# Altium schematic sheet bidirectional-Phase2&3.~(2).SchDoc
size 431 x 279 mm; Date: Not shown in title block; ApprovedBy: Not shown in title block; CheckedBy: Not shown in title block; Author: Not shown in title block; CompanyName: Not shown in title block; Engineer: Not shown in title block; Organization: Not shown in title block; Address1: Not shown in title block; Address2: Not shown in title block; Address3: Not shown in title block; Address4: Not shown in title block; DocumentNumber: 5; Revision: Use project parameter SCH_Rev; SheetNumber: 5; SheetTotal: 6; PageSetup: Record=PageOptions|CenterHorizontal=True|CenterVertical=True|PrintScale=0.96|XCorrection=1.00|YCorrection=1.00|PrintKind=0|BorderSize=5000000|LeftOffset=0|BottomOffset=0|Orientation=2|PaperLength=1000|PaperWidth=1000|Scale=100|PaperSource=15|PrintQuality=600|MediaType=1|DitherType=10|PaperKind=11x17|PrintScaleMode=1
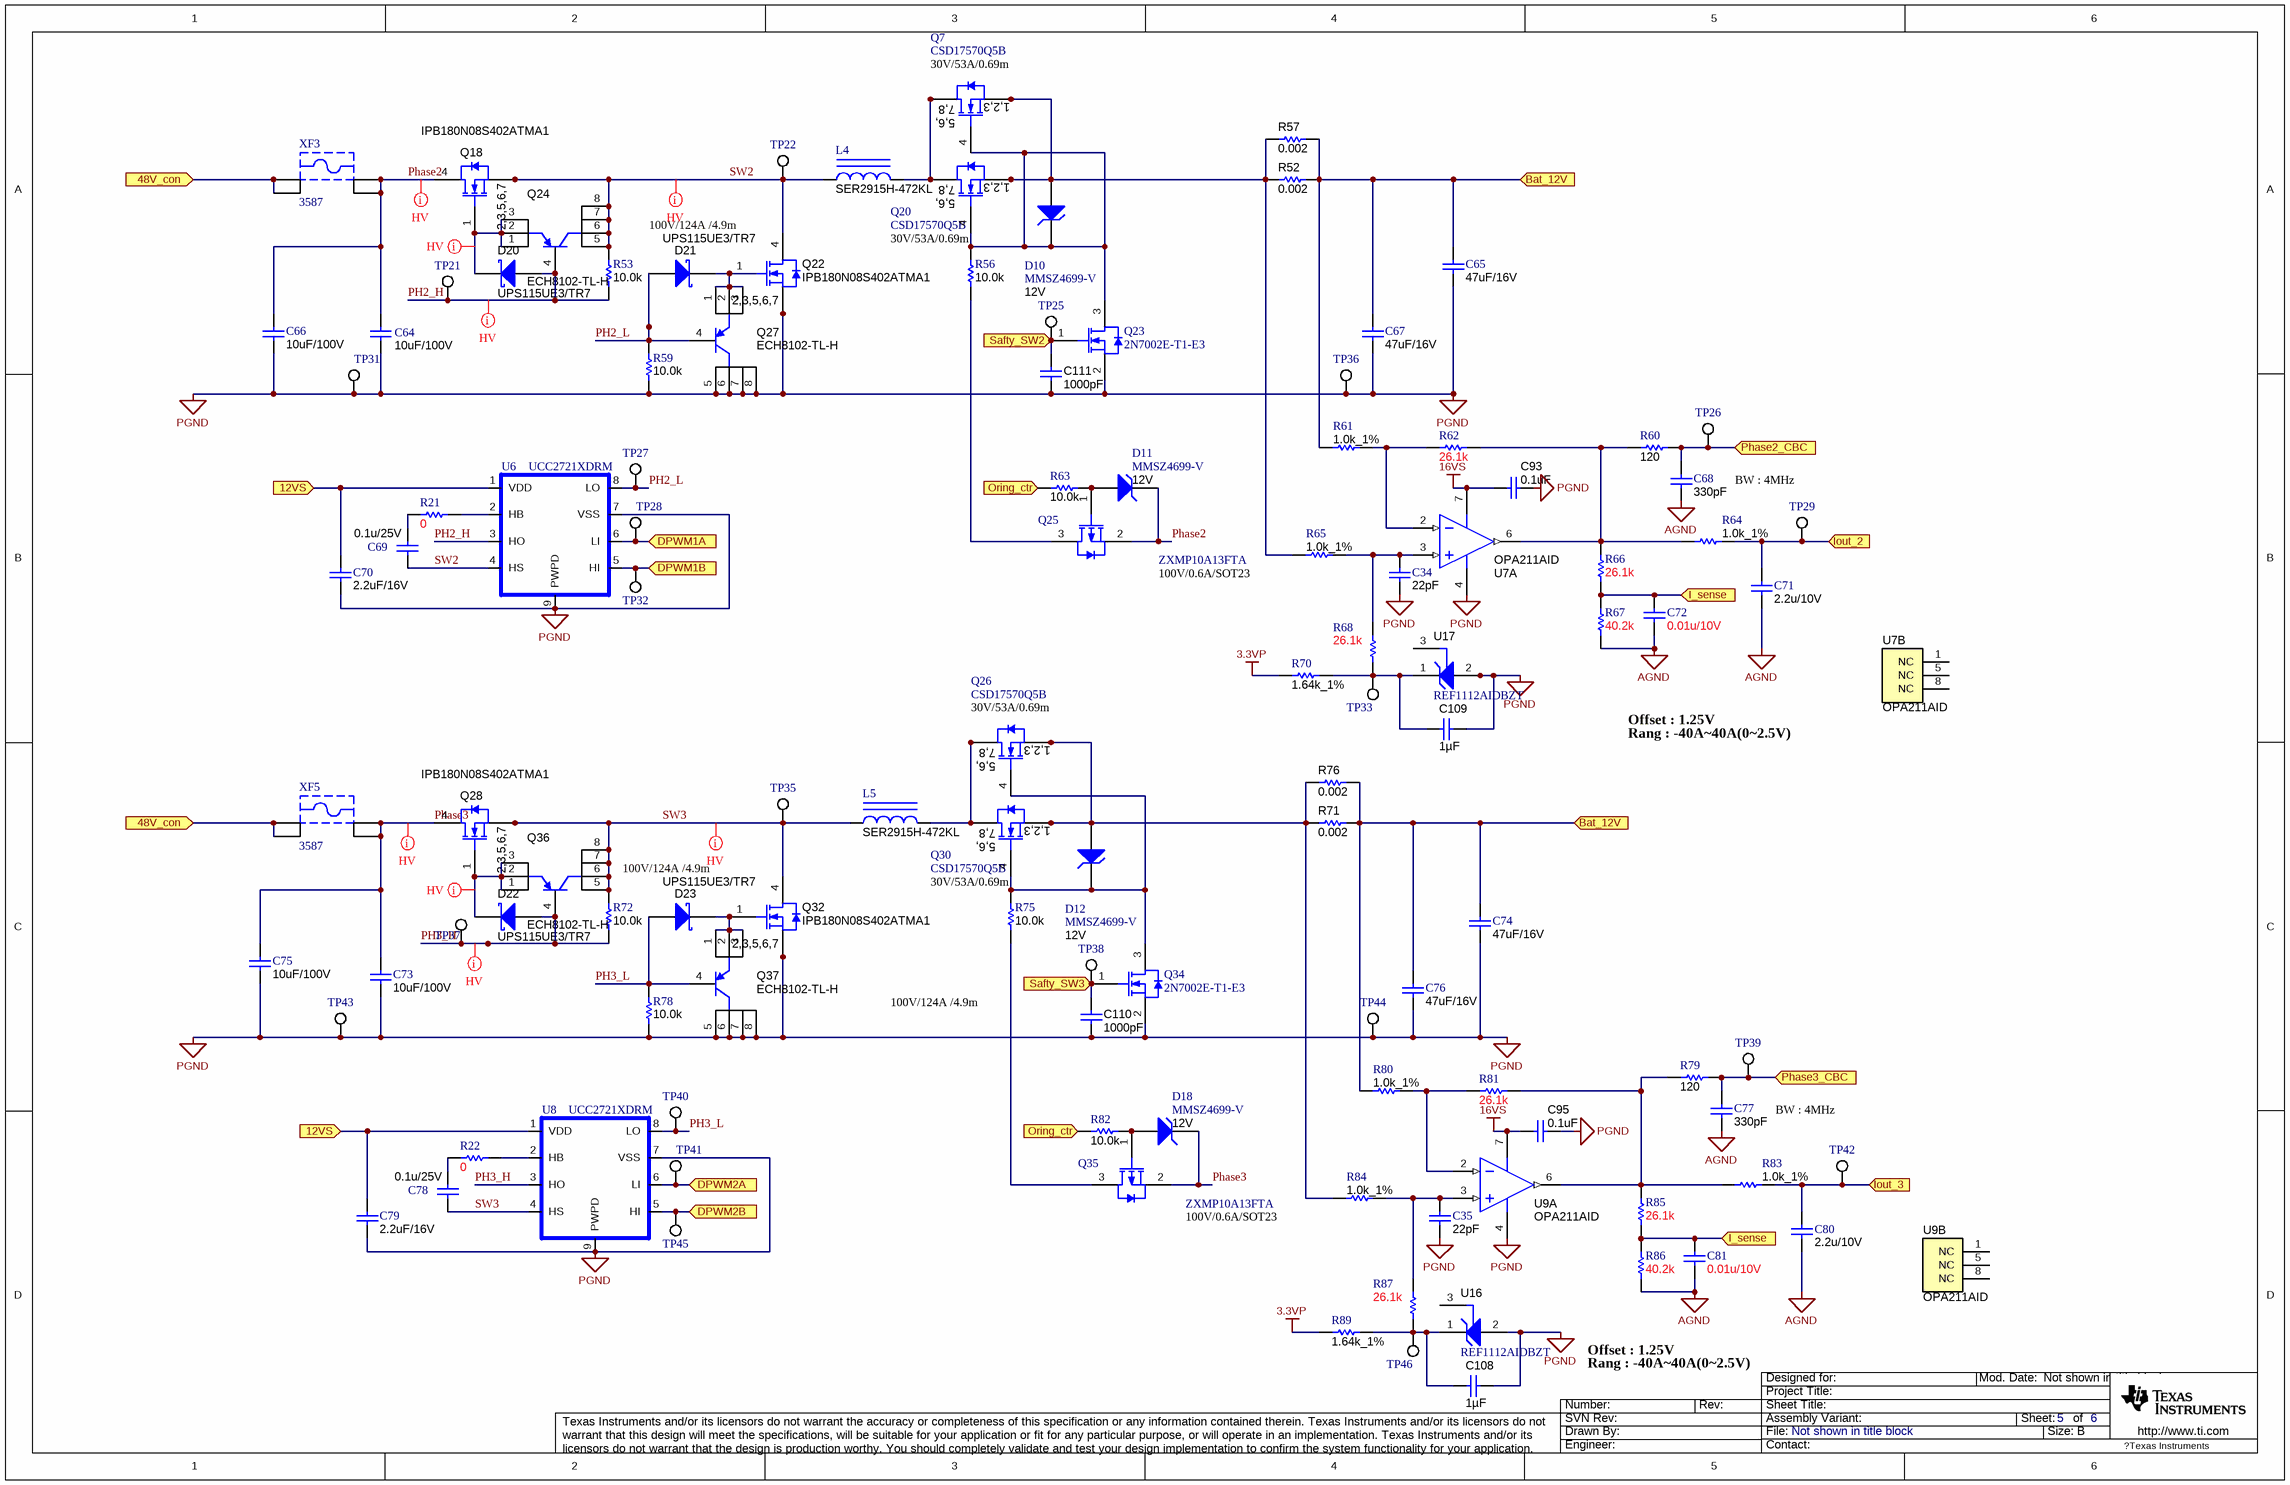
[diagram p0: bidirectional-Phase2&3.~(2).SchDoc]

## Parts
C34  ValueDisplayed: 22pF  [0603]  (hidden comment: 06035A220JAT2A)
C35  ValueDisplayed: 22pF  [0603]  (hidden comment: 06035A220JAT2A)
C64  ValueDisplayed: 10uF/100V  [2220]  (hidden comment: C5750X7S2A106M)
C65  ValueDisplayed: 47uF/16V  [1210]  (hidden comment: GRM32ER61C476ME15L)
C66  ValueDisplayed: 10uF/100V  [2220]  (hidden comment: C5750X7S2A106M)
C67  ValueDisplayed: 47uF/16V  [1210]  (hidden comment: GRM32ER61C476ME15L)
C68  ValueDisplayed: 330pF  [0603]  (hidden comment: 06035A331JAT2A)
C69  ValueDisplayed: 0.1u/25V  [0603]  (hidden comment: 06033C104KAT2A)
C70  ValueDisplayed: 2.2uF/16V  [0805_HV]  (hidden comment: 0805YD225KAT2A)
C71  ValueDisplayed: 2.2u/10V  [0603]  (hidden comment: C0603C225K8PACTU)
C72  ValueDisplayed: 0.01u/10V  [0603]  (hidden comment: 06031C103JAT2A)
C73  ValueDisplayed: 10uF/100V  [2220]  (hidden comment: C5750X7S2A106M)
C74  ValueDisplayed: 47uF/16V  [1210]  (hidden comment: GRM32ER61C476ME15L)
C75  ValueDisplayed: 10uF/100V  [2220]  (hidden comment: C5750X7S2A106M)
C76  ValueDisplayed: 47uF/16V  [1210]  (hidden comment: GRM32ER61C476ME15L)
C77  ValueDisplayed: 330pF  [0603]  (hidden comment: 06035A331JAT2A)
C78  ValueDisplayed: 0.1u/25V  [0603]  (hidden comment: 06033C104KAT2A)
C79  ValueDisplayed: 2.2uF/16V  [0805_HV]  (hidden comment: 0805YD225KAT2A)
C80  ValueDisplayed: 2.2u/10V  [0603]  (hidden comment: C0603C225K8PACTU)
C81  ValueDisplayed: 0.01u/10V  [0603]  (hidden comment: 06031C103JAT2A)
C93  ValueDisplayed: 0.1uF  [0603]  (hidden comment: 06033C104JAT2A)
C95  ValueDisplayed: 0.1uF  [0603]  (hidden comment: 06033C104JAT2A)
C108  ValueDisplayed: 1µF  [0603_095]  (hidden comment: C0603C105K3RACTU)
C109  ValueDisplayed: 1µF  [0603_095]  (hidden comment: C0603C105K3RACTU)
C110  ValueDisplayed: 1000pF  [0603]  (hidden comment: C0603X102K5RACTU)
C111  ValueDisplayed: 1000pF  [0603]  (hidden comment: C0603X102K5RACTU)
D10  MMSZ4699-V  value 12V  [SOD-123]
D11  MMSZ4699-V  value 12V  [SOD-123]
D12  MMSZ4699-V  value 12V  [SOD-123]
D18  MMSZ4699-V  value 12V  [SOD-123]
D20  UPS115UE3/TR7  [DO-216AA]
D21  UPS115UE3/TR7  [DO-216AA]
D22  UPS115UE3/TR7  [DO-216AA]
D23  UPS115UE3/TR7  [DO-216AA]
L4  SER2915H-472KL  [SER2915H]
L5  SER2915H-472KL  [SER2915H]
Q7  CSD17570Q5B  [TRANS_NexFET_Q5B]
Q18  IPB180N08S402ATMA1  [DDPAK-7]
Q20  CSD17570Q5B  [TRANS_NexFET_Q5B]
Q22  IPB180N08S402ATMA1  [DDPAK-7]
Q23  2N7002E-T1-E3  [SOT-23]
Q24  ECH8102-TL-H  [ECH8]
Q25  ZXMP10A13FTA  [SOT-23]
Q26  CSD17570Q5B  [TRANS_NexFET_Q5B]
Q27  ECH8102-TL-H  [ECH8]
Q28  IPB180N08S402ATMA1  [DDPAK-7]
Q30  CSD17570Q5B  [TRANS_NexFET_Q5B]
Q32  IPB180N08S402ATMA1  [DDPAK-7]
Q34  2N7002E-T1-E3  [SOT-23]
Q35  ZXMP10A13FTA  [SOT-23]
Q36  ECH8102-TL-H  [ECH8]
Q37  ECH8102-TL-H  [ECH8]
R21  value 0  [0603]  (hidden comment: MCR03EZPJ000)
R22  value 0  [0603]  (hidden comment: MCR03EZPJ000)
R52  ValueDisplayed: 0.002  [2512]  (hidden comment: ERJ-M1WTF2M0U)
R53  value 10.0k  [0603]  (hidden comment: RG1608P-103-B-T5)
R56  ValueDisplayed: 10.0k  [0603]  (hidden comment: CRCW060310K0FKEA)
R57  ValueDisplayed: 0.002  [2512]  (hidden comment: ERJ-M1WTF2M0U)
R59  value 10.0k  [0603]  (hidden comment: RG1608P-103-B-T5)
R60  ValueDisplayed: 120  [0603]  (hidden comment: CRCW0603120RJNEA)
R61  value 1.0k_1%  [0603]  (hidden comment: CRCW06031K00JNEA)
R62  value 26.1k  [0603]  (hidden comment: CRCW060326K1FKEA)
R63  ValueDisplayed: 10.0k  [0603]  (hidden comment: CRCW060310K0FKEA)
R64  value 1.0k_1%  [0603]  (hidden comment: CRCW06031K00JNEA)
R65  value 1.0k_1%  [0603]  (hidden comment: CRCW06031K00JNEA)
R66  value 26.1k  [0603]  (hidden comment: CRCW060326K1FKEA)
R67  value 40.2k  [0603]  (hidden comment: CRCW060340K2FKEA)
R68  value 26.1k  [0603]  (hidden comment: CRCW060326K1FKEA)
R70  value 1.64k_1%  [0603]  (hidden comment: CRCW06031K65FKEA)
R71  ValueDisplayed: 0.002  [2512]  (hidden comment: ERJ-M1WTF2M0U)
R72  value 10.0k  [0603]  (hidden comment: RG1608P-103-B-T5)
R75  ValueDisplayed: 10.0k  [0603]  (hidden comment: CRCW060310K0FKEA)
R76  ValueDisplayed: 0.002  [2512]  (hidden comment: ERJ-M1WTF2M0U)
R78  value 10.0k  [0603]  (hidden comment: RG1608P-103-B-T5)
R79  ValueDisplayed: 120  [0603]  (hidden comment: CRCW0603120RJNEA)
R80  value 1.0k_1%  [0603]  (hidden comment: CRCW06031K00JNEA)
R81  value 26.1k  [0603]  (hidden comment: CRCW060326K1FKEA)
R82  ValueDisplayed: 10.0k  [0603]  (hidden comment: CRCW060310K0FKEA)
R83  value 1.0k_1%  [0603]  (hidden comment: CRCW06031K00JNEA)
R84  value 1.0k_1%  [0603]  (hidden comment: CRCW06031K00JNEA)
R85  value 26.1k  [0603]  (hidden comment: CRCW060326K1FKEA)
R86  value 40.2k  [0603]  (hidden comment: CRCW060340K2FKEA)
R87  value 26.1k  [0603]  (hidden comment: CRCW060326K1FKEA)
R89  value 1.64k_1%  [0603]  (hidden comment: CRCW06031K65FKEA)
TP21  5002  [Keystone5002]  (value not drawn)
TP22  5002  [Keystone5002]  (value not drawn)
TP25  5002  [Keystone5002]  (value not drawn)
TP26  5002  [Keystone5002]  (value not drawn)
TP27  5002  [Keystone5002]  (value not drawn)
TP28  5002  [Keystone5002]  (value not drawn)
TP29  5002  [Keystone5002]  (value not drawn)
TP31  5002  [Keystone5002]  (value not drawn)
TP32  5002  [Keystone5002]  (value not drawn)
TP33  5002  [Keystone5002]  (value not drawn)
TP35  5002  [Keystone5002]  (value not drawn)
TP36  5002  [Keystone5002]  (value not drawn)
TP37  5002  [Keystone5002]  (value not drawn)
TP38  5002  [Keystone5002]  (value not drawn)
TP39  5002  [Keystone5002]  (value not drawn)
TP40  5002  [Keystone5002]  (value not drawn)
TP41  5002  [Keystone5002]  (value not drawn)
TP42  5002  [Keystone5002]  (value not drawn)
TP43  5002  [Keystone5002]  (value not drawn)
TP44  5002  [Keystone5002]  (value not drawn)
TP45  5002  [Keystone5002]  (value not drawn)
TP46  5002  [Keystone5002]  (value not drawn)
U6  UCC2721XDRM  [DRM0008A]
U7  OPA211AID  [D0008A_N]  (parts A,B of 2)
U8  UCC2721XDRM  [DRM0008A]
U9  OPA211AID  [D0008A_N]  (parts A,B of 2)
U16  REF1112AIDBZT  [DBZ0003A_N]
U17  REF1112AIDBZT  [DBZ0003A_N]
XF3  3587  [KEYSTONE_3587]
XF5  3587  [KEYSTONE_3587]

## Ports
12VS, 48V_con, Bat_12V, DPWM1A, DPWM1B, DPWM2A, DPWM2B, I_sense, Iout_2, Iout_3, Oring_ctr, Phase2_CBC, Phase3_CBC, Safty_SW2, Safty_SW3

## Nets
3.3VP: R70.1 R89.1
16VS: C93.2 C95.2 U7.7(V+) U9.7(V+)
AGND: C68.2 C71.2 C72.2 C77.2 C80.2 C81.2 R67.1 R86.1
PGND: C34.2 C35.2 C64.2 C65.2 C66.2 C67.2 C70.2 C73.2 C74.2 C75.2 C76.2 C79.2 C93.1 C95.1 C108.1 C109.1 C110.2 C111.2 Q22.2(S) Q22.3(S) Q22.5(S) Q22.6(S) Q22.7(S) Q23.2(S) Q27.5(C) Q27.6(C) Q27.7(C) Q27.8(C) Q32.2(S) Q32.3(S) Q32.5(S) Q32.6(S) Q32.7(S) Q34.2(S) Q37.5(C) Q37.6(C) Q37.7(C) Q37.8(C) R59.1 R78.1 TP31.1 TP36.1 TP43.1 TP44.1 U6.7(VSS) U6.9(PWPD) U7.4(V-) U8.7(VSS) U8.9(PWPD) U9.4(V-) U16.2(GND) U17.2(GND)
12VS: C70.1 C79.1 U6.1(VDD) U8.1(VDD) ; port 12VS
48V_con: XF3.1 XF3.2 XF5.1 XF5.2 ; port 48V_con
Bat_12V: C65.1 C67.1 C74.1 C76.1 R52.2 R57.2 R61.1 R71.2 R76.2 R80.1 ; port Bat_12V
DPWM1A: TP28.1 U6.6(LI) ; port DPWM1A
DPWM1B: TP32.1 U6.5(HI) ; port DPWM1B
DPWM2A: TP41.1 U8.6(LI) ; port DPWM2A
DPWM2B: TP45.1 U8.5(HI) ; port DPWM2B
I_sense: C72.1 C81.1 R66.1 R67.2 R85.1 R86.2 ; port I_sense
Iout_2: C71.1 R64.2 TP29.1 ; port Iout_2
Iout_3: C80.1 R83.2 TP42.1 ; port Iout_3
Oring_ctr: R63.2 R82.2 ; port Oring_ctr
PH2_H: D20.2(A) Q24.4(B) R53.1 TP21.1 U6.3(HO)
PH2_L: D21.2(A) Q27.4(B) R59.2 TP27.1 U6.8(LO)
PH3_H: D22.2(A) Q36.4(B) R72.1 TP37.1 U8.3(HO)
PH3_L: D23.2(A) Q37.4(B) R78.2 TP40.1 U8.8(LO)
Phase2: C64.1 C66.1 D11.1(K) Q18.4(D) Q25.2(S) XF3.3 XF3.4
Phase2_CBC: C68.1 R60.2 TP26.1 ; port Phase2_CBC
Phase3: C73.1 C75.1 D18.1(K) Q28.4(D) Q35.2(S) XF5.3 XF5.4
Phase3_CBC: C77.1 R79.2 TP39.1 ; port Phase3_CBC
Safty_SW2: C111.1 Q23.1(G) TP25.1 ; port Safty_SW2
Safty_SW3: C110.1 Q34.1(G) TP38.1 ; port Safty_SW3
SW2: C69.2 L4.1 Q18.2(S) Q18.3(S) Q18.5(S) Q18.6(S) Q18.7(S) Q22.4(D) Q24.5(C) Q24.6(C) Q24.7(C) Q24.8(C) R53.2 TP22.1 U6.4(HS)
SW3: C78.2 L5.1 Q28.2(S) Q28.3(S) Q28.5(S) Q28.6(S) Q28.7(S) Q32.4(D) Q36.5(C) Q36.6(C) Q36.7(C) Q36.8(C) R72.2 TP35.1 U8.4(HS)
NetC34_1: C34.1 R65.2 R68.2 U7.3(IN+)
NetC35_1: C35.1 R84.2 R87.2 U9.3(IN+)
NetC69_1: C69.1 R21.1
NetC78_1: C78.1 R22.1
NetC108_2: C108.2 R87.1 R89.2 TP46.1 U16.1(VO)
NetC109_2: C109.2 R68.1 R70.2 TP33.1 U17.1(VO)
NetD10_1: D10.1(K) Q7.4(G) Q20.4(G) Q23.3(D) R56.2
NetD10_2: D10.2(A) Q7.1(S) Q7.2(S) Q7.3(S) Q20.1(S) Q20.2(S) Q20.3(S) R52.1 R57.1 R65.1
NetD11_2: D11.2(A) Q25.1(G) R63.1
NetD12_1: D12.1(K) Q26.4(G) Q30.4(G) Q34.3(D) R75.2
NetD12_2: D12.2(A) Q26.1(S) Q26.2(S) Q26.3(S) Q30.1(S) Q30.2(S) Q30.3(S) R71.1 R76.1 R84.1
NetD18_2: D18.2(A) Q35.1(G) R82.1
NetD20_1: D20.1(K) Q18.1(G) Q24.1(E) Q24.2(E) Q24.3(E)
NetD21_1: D21.1(K) Q22.1(G) Q27.1(E) Q27.2(E) Q27.3(E)
NetD22_1: D22.1(K) Q28.1(G) Q36.1(E) Q36.2(E) Q36.3(E)
NetD23_1: D23.1(K) Q32.1(G) Q37.1(E) Q37.2(E) Q37.3(E)
NetL4_2: L4.2 Q7.5(D) Q7.6(D) Q7.7(D) Q7.8(D) Q20.5(D) Q20.6(D) Q20.7(D) Q20.8(D)
NetL5_2: L5.2 Q26.5(D) Q26.6(D) Q26.7(D) Q26.8(D) Q30.5(D) Q30.6(D) Q30.7(D) Q30.8(D)
NetQ25_3: Q25.3(D) R56.1
NetQ35_3: Q35.3(D) R75.1
NetR21_2: R21.2 U6.2(HB)
NetR22_2: R22.2 U8.2(HB)
NetR60_1: R60.1 R62.2 R64.1 R66.2 U7.6(OUT)
NetR61_2: R61.2 R62.1 U7.2(IN-)
NetR79_1: R79.1 R81.2 R83.1 R85.2 U9.6(OUT)
NetR80_2: R80.2 R81.1 U9.2(IN-)

Not connected (* = marked no-connect by the designer): U7 1(NC) 5(NC) 8(NC); U9 1(NC) 5(NC) 8(NC); U16 3(NC); U17 3(NC)

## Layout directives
net class HV: NetD20_1, NetD22_1, PH2_H, PH3_H, Phase2, Phase3, SW2, SW3

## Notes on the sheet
- (near Q7) 30V/53A/0.69m
- 100V/124A /4.9m
- (near R56) 30V/53A/0.69m
- BW : 4MHz
- 100V/0.6A/SOT23
- (near Q26) 30V/53A/0.69m
- Offset : 1.25V
- Rang : -40A~40A(0|.5V)
- (near R75) 30V/53A/0.69m

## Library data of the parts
C34 C35 = 06035A220JAT2A: CAP, CERM, 22pF, 50V, +/-5%, C0G/NP0, 0603; Manufacturer: AVX; Polarized: N; CompType: Capacitor; U/M: EA; Cap_F: 0.000000000022; Tolerance_%: 5; ESR_Ohm: 0.259; Value1: 0.259 ohm; VDC_V: 50; TaMin_C: -55; TaMax_C: 125
C64 C66 C73 C75 = C5750X7S2A106M: CAP, CERM, 10uF, 100V, +/-20%, X7S, 2220; Manufacturer: TDK; Polarized: N; CompType: Capacitor; U/M: EA; Cap_F: 0.00001; Tolerance_%: 20; ESR_Ohm: 0.005; Value1: 0.005 ohm; VDC_V: 100; IRMS_A: 6.45; TaMin_C: -55; TaMax_C: 125
C65 C67 C74 C76 = GRM32ER61C476ME15L: CAP, CERM, 47uF, 16V, +/-20%, X5R, 1210; Manufacturer: MuRata; Polarized: N; CompType: Capacitor; U/M: EA; Cap_F: 0.000047; Tolerance_%: 20; ESR_Ohm: 0.002; Value1: 0.002 ohm; VDC_V: 16; TaMin_C: -55; TaMax_C: 85
C68 C77 = 06035A331JAT2A: CAP, CERM, 330pF, 50V, +/-5%, C0G/NP0, 0603; Manufacturer: AVX; Polarized: N; CompType: Capacitor; U/M: EA; Cap_F: 0.00000000033; Tolerance_%: 5; ESR_Ohm: 0.071; Value1: 0.071 ohm; VDC_V: 50; TaMin_C: -55; TaMax_C: 125
C69 C78 = 06033C104KAT2A: CAP, CERM, 0.1uF, 25V, +/-10%, X7R, 0603; Manufacturer: AVX; Polarized: N; CompType: Capacitor; U/M: EA; Cap_F: 0.0000001; Tolerance_%: 10; ESR_Ohm: 0.05; Value1: 0.05 ohm; VDC_V: 25; TaMin_C: -55; TaMax_C: 125
C70 C79 = 0805YD225KAT2A: CAP, CERM, 2.2uF, 16V, +/-10%, X5R, 0805; Manufacturer: AVX; Polarized: N; CompType: Capacitor; U/M: EA; Cap_F: 0.0000022; Tolerance_%: 10; ESR_Ohm: 0.009; Value1: 0.009 ohm; VDC_V: 16; TaMin_C: -55; TaMax_C: 85; Cap_Case: 0805
C71 C80 = C0603C225K8PACTU: CAP, CERM, 2.2uF, 10V, +/-10%, X5R, 0603; Manufacturer: Kemet; Polarized: N; CompType: Capacitor; U/M: EA; Cap_F: 0.0000022; Tolerance_%: 10; Value1: Unknown; TaMin_C: -55; TaMax_C: 85
C72 C81 = 06031C103JAT2A: CAP, CERM, 0.01uF, 100V, +/-5%, X7R, 0603; Manufacturer: AVX; Polarized: N; CompType: Capacitor; U/M: EA; Cap_F: 0.00000001; Tolerance_%: 5; ESR_Ohm: 0.098; Value1: 0.098 ohm; VDC_V: 100; TaMin_C: -55; TaMax_C: 125
C93 C95 = 06033C104JAT2A: CAP, CERM, 0.1uF, 25V, +/-5%, X7R, 0603; Manufacturer: AVX; Polarized: N; CompType: Capacitor; U/M: EA; Cap_F: 0.0000001; Tolerance_%: 5; ESR_Ohm: 0.05; Value1: 0.05 ohm; VDC_V: 25; TaMin_C: -55; TaMax_C: 125
C108 C109 = C0603C105K3RACTU: CAP, CERM, 1 µF, 25 V, +/- 10%, X7R, 0603_095; Manufacturer: Kemet; Polarized: N; CompType: Capacitor; Value: 1uF; U/M: EA; Cap_F: 0.000001; Tolerance_%: 10; Value1: Unknown; VDC_V: 25; Value2: 25V; TaMin_C: -55; TaMax_C: 125; Cap_Case: 0603
C110 C111 = C0603X102K5RACTU: CAP, CERM, 1000 pF, 50 V, +/- 10%, X7R, 0603; Manufacturer: Kemet; Polarized: N; CompType: Capacitor; Value: 1000pF; U/M: EA; Cap_F: 0.000000001; Tolerance_%: 10; Value1: Unknown; VDC_V: 50; Value2: 50V; TaMin_C: -55; TaMax_C: 125
D10-D12 D18 = MMSZ4699-V: Diode, Zener, 12V, 500mW, SOD-123; Manufacturer: Vishay-Semiconductor; SymbolCreator: a0412235; U/M: EA; Power_W: 0.5; Vz_V: 12; Value1: 0.5W; RJA_CperW: 67
D20-D23 = UPS115UE3/TR7: Diode, Schottky, 15 V, 1 A, DO-216-AA; Manufacturer: Microsemi; U/M: EA; Vf_V: 0.31; Value: 15V; Value1: 1A; Value2: 0.31V; Io_A: 1; Vr_V: 15; TJmax_C: 100
L4 L5 = SER2915H-472KL: Inductor, Shielded E Core, Ferrite, 4.7 µH, 30 A, 0.00186 ohm, SMD; Manufacturer: Coilcraft; Value: 4.7uH; Ind_H: 4.7E-6; ValueDisplayed: 4.7µH; Imax_A: 30; Irms: 30A @ 40C rise; Isat: 50.1A @ 30% inductance drop; Value2: 30A
Q7 Q20 Q26 Q30 = CSD17570Q5B: MOSFET, N-CH, 30V, 51A, SON 5x6mm; Manufacturer: Texas Instruments; Alternate Manufacturer: None; U/M: EA; ChType: N; VdsMax_V: 30; Value1: 0.0076 ohm; Rdson45_Ohm: 0.0076; Value2: 97 nC; QgTyp_nC: 97; Vgs_V: 20; IdsMax_A: 51
Q18 Q22 Q28 Q32 = IPB180N08S402ATMA1: MOSFET, N-CH, 80 V, 180 A, DDPAK-7; Manufacturer: Infineon Technologies; Alternate Manufacturer: None; SymbolCreator: a0412235; U/M: EA; ChType: N; Value: 80V; VdsMax_V: 80; Value1: ? ohm; Value2: 128 nC; QgTyp_nC: 128; Vgs_V: 20; IdsMax_A: 180
Q23 Q34 = 2N7002E-T1-E3: MOSFET, N-CH, 60V, 0.24A, SOT-23; Manufacturer: Vishay-Siliconix; Alternate Manufacturer: None; U/M: EA; ChType: N; VdsMax_V: 60; Value1: 1.8 ohm; Rdson45_Ohm: 1.8; Value2: 0.4 nC; QgTyp_nC: 0.4; Vgs_V: 20; IdsMax_A: 0.24
Q24 Q27 Q36 Q37 = ECH8102-TL-H, ON Semiconductor: Transistor, PNP, 30 V, 12 A, SMD-8; CompType: BJT; PNP: 1; NPN: 0; Vceo_V: 30; Vcesat1_V: 0.08; Value: 30 V; IcRated_A: 12; Value1: 12 A; HfeMax: 560; TaMin_C: -55; TaMax_C: 150; U/M: EA
Q25 Q35 = ZXMP10A13FTA: MOSFET, P-CH, -100V, -0.6A, SOT-23; Manufacturer: Diodes Inc.; Alternate Manufacturer: None; U/M: EA; ChType: P; VdsMax_V: -100; Value1: 1 ohm; Rdson45_Ohm: 1; Value2: 3.5 nC; QgTyp_nC: 3.5; Vgs_V: -4; IdsMax_A: -0.6
R21 R22 = MCR03EZPJ000: RES, 0 ohm, 5%, 0.1W, 0603; Manufacturer: Rohm; CompType: Resistor; Value_Code: 0000; Tolerance_%: 5; Power_W: 0.1; VDC_V: 50; TempCo: 400 ppm/C; EIA_Code: E24; U/M: EA
R52 R57 R71 R76 = ERJ-M1WTF2M0U: RES, 0.002, 1%, 1 W, 2512; Manufacturer: Panasonic; CompType: Resistor; Value: 0.002; Value_Code: 2L000; Tolerance_%: 1; Value2: 1W; TempCo: ppm/C; U/M: EA
R53 R59 R72 R78 = RG1608P-103-B-T5: RES, 10.0k ohm, 0.1%, 0.1W, 0603; Manufacturer: Susumu Co Ltd; CompType: Resistor; Res_ohm: 10000; Value_Code: 10k0; Tolerance_%: 0.1; VDC_V: 75; TempCo: 25 ppm/C; EIA_Code: E192; U/M: EA
R56 R63 R75 R82 = CRCW060310K0FKEA: RES, 10.0 k, 1%, 0.1 W, 0603; Manufacturer: Vishay-Dale; CompType: Resistor; Value: 10.0k; Res_ohm: 10000; Value_Code: 10k0; Tolerance_%: 1; Power_W: 0.1; Value2: 0.1W; VDC_V: 75; TempCo: 100 ppm/C; EIA_Code: E96; U/M: EA
R60 R79 = CRCW0603120RJNEA: RES, 120, 5%, 0.1 W, 0603; Manufacturer: Vishay-Dale; CompType: Resistor; Value: 120; Value_Code: 120R; Tolerance_%: 5; Power_W: 0.1; Value2: 0.1W; VDC_V: 75; TempCo: 200 ppm/C; EIA_Code: E24; U/M: EA
R61 R64 R65 R80 R83 R84 = CRCW06031K00JNEA: RES, 1.0k ohm, 5%, 0.1W, 0603; Manufacturer: Vishay-Dale; CompType: Resistor; Res_ohm: 1000; Value_Code: 1k00; Tolerance_%: 5; Power_W: 0.1; VDC_V: 75; TempCo: 200 ppm/C; EIA_Code: E24; U/M: EA
R62 R66 R68 R81 R85 R87 = CRCW060326K1FKEA: RES, 26.1k ohm, 1%, 0.1W, 0603; Manufacturer: Vishay-Dale; CompType: Resistor; Res_ohm: 26100; Value_Code: 26k1; Tolerance_%: 1; Power_W: 0.1; VDC_V: 75; TempCo: 100 ppm/C; EIA_Code: E96; U/M: EA
R67 R86 = CRCW060340K2FKEA: RES, 40.2k ohm, 1%, 0.1W, 0603; Manufacturer: Vishay-Dale; CompType: Resistor; Res_ohm: 40200; Value_Code: 40k2; Tolerance_%: 1; Power_W: 0.1; VDC_V: 75; TempCo: 100 ppm/C; EIA_Code: E96; U/M: EA
R70 R89 = CRCW06031K65FKEA: RES, 1.65k ohm, 1%, 0.1W, 0603; Manufacturer: Vishay-Dale; CompType: Resistor; Res_ohm: 1650; Value_Code: 1k65; Tolerance_%: 1; Power_W: 0.1; VDC_V: 75; TempCo: 100 ppm/C; EIA_Code: E96; U/M: EA
TP21 TP22 TP25-TP29 TP31-TP33 TP35-TP46 = 5002: Test Point, Miniature, White, TH; Manufacturer: Keystone; CompType: Test Point Loop; U/M: EA
U6 U8 = UCC2721XDRM: IC, 120V Boot, 4A Peak, High Frequency High-Side Low-Side Driver; Manufacturer: TI; Alternate Manufacturer: None; Area: 41800
U7 U9 = OPA211AID: 1.1 nV/rtHz Noise, Low Power, Precision Operational Amplifier, 4.5 to 36 V, -40 to 125 degC, 8-pin SOIC (D0008A), Green (RoHS & no Sb/Br); Manufacturer: Texas Instruments; Alternate PartNumber: Equivalent; CMRR(Min)(dB): 114; GBW(Typ)(MHz): 45; IIB(Max)(pA): 175000; Iq per channel(Max)(mA): 4.5; Number of Channels: 1; Offset Drift(Typ)(uV/C): 0.15; Packing: TUBE; Rating: Catalog; Slew Rate(Typ)(V/us): 27; Sub Family: High Supply Voltage Amplifier (>=30V), Low Noise Amp (<=10nV/rtHz), Low Offset Voltage Amplifier (<=500uV), Precision Amplifier; Total Supply Voltage(Max)(+5V is 5, +/-5V is 10): 36; Vio (25C)(Max)(mV): 0.125
U16 U17 = REF1112AIDBZt: 1 uA Shunt Voltage Reference, 1.25 V, 10 ppm / degC, 5 mA, -40 to 85 degC, 3-pin SOT-23 (DBZ), Green (RoHS & no Sb/Br); Manufacturer: Texas Instruments; Alternate PartNumber: Equivalent; Initial Accuracy @ 25/deg C(%): 0.2; Iout/Iz(Max)(mA): 5; Min Iz for Regulation(uA): 1.2; Rating: Catalog; Temp Coeff(Max)(ppm/ degree C): 50; Temp Coeff(Typ)(ppm/ degree C): 10; VO(V): 1.25
XF3 XF5 = 3587: FuseHolder; Manufacturer: Keystone; SymbolCreator: a0799628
